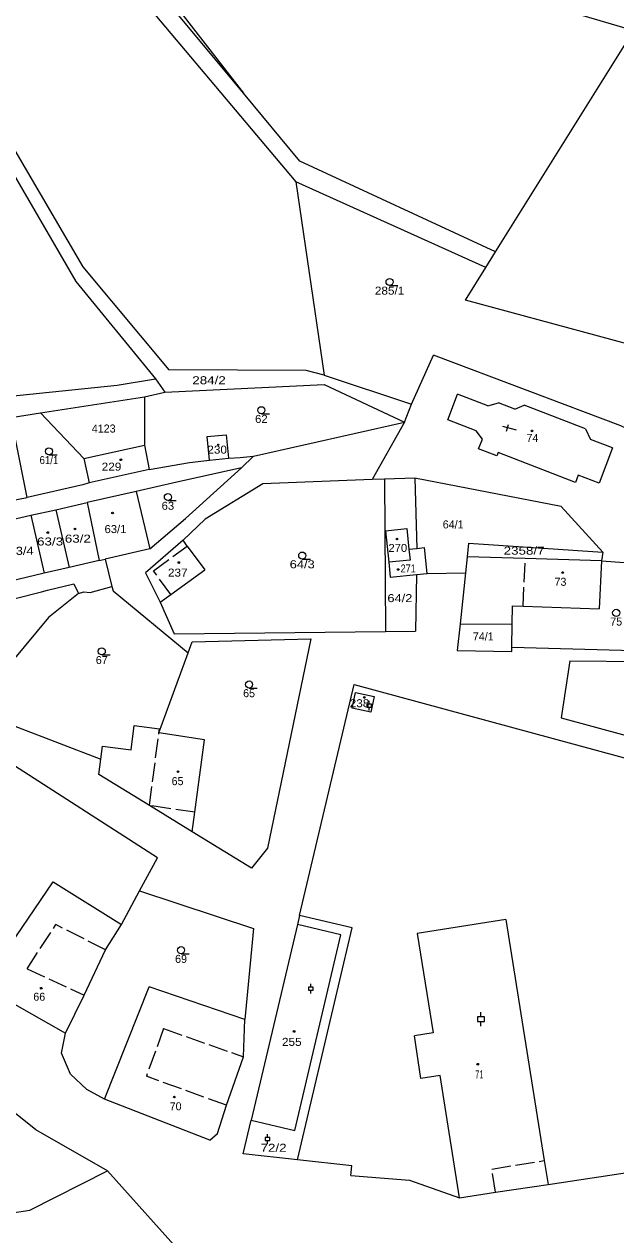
# Model space of a CAD drawing. Extents: x -590528 to -586543, y -1119609 to -1116685.
# Drawn here: x -589161.2 to -589035.6, y -1118589.8 to -1118332.6 of the extents above; entities that cross this region are included whole.
import ezdxf
from ezdxf.enums import TextEntityAlignment as Align

# ---------------------------------------------------------------- set-up
doc = ezdxf.new("R2010")
doc.units = 0
doc.header["$LTSCALE"] = 0.68
doc.linetypes.add('LONG_DASHED', pattern=[7.5, 6, -1.5])
for name, color, linetype, lineweight in [('1', 7, 'Continuous', 13), ('2', 7, 'LONG_DASHED', 13), ('3', 7, 'Continuous', 13), ('6', 7, 'Continuous', 13)]:
    doc.layers.add(name, color=color, linetype=linetype, lineweight=lineweight)

msp = doc.modelspace()

# ---------------------------------------------------------------- linework, layer by layer
at = {"layer": '1'}
for p, q in [((-589153.28, -1118297.42), (-589114.64, -1118347.32)), ((-589114.64, -1118347.32), (-589150.17, -1118304.55)), ((-589152.4, -1118308.08), (-589103.56, -1118366.12)), ((-589061.12, -1118380.96), (-589031.78, -1118334)), ((-589102.65, -1118361.74), (-589114.64, -1118347.32)), ((-589167.9, -1118351.48), (-589148.72, -1118384.16)), ((-589167.93, -1118356.86), (-589150.27, -1118387.26)), ((-589061.12, -1118380.96), (-589102.65, -1118361.74)), ((-589103.56, -1118366.12), (-589097.53, -1118407.21)), ((-589063.22, -1118384.32), (-589103.56, -1118366.12)), ((-589148.72, -1118384.16), (-589130.5, -1118406.04)), ((-589150.27, -1118387.26), (-589133.34, -1118408)), ((-589015.88, -1118405.31), (-589067.54, -1118391.23)), ((-589141.45, -1118409.35), (-589133.34, -1118408)), ((-589133.34, -1118408), (-589131.35, -1118410.84)), ((-589157.76, -1118415.19), (-589135.66, -1118411.8)), ((-589135.66, -1118411.8), (-589135.68, -1118422.1)), ((-589135.66, -1118411.8), (-589131.35, -1118410.84)), ((-589071.29, -1118416.65), (-589069.19, -1118411.22)), ((-589062.75, -1118413.71), (-589069.19, -1118411.22)), ((-589080.44, -1118417.2), (-589078.97, -1118413.35)), ((-589062.75, -1118413.71), (-589060.48, -1118413.09)), ((-589057.03, -1118414.42), (-589060.48, -1118413.09)), ((-589057.03, -1118414.42), (-589055.09, -1118413.56)), ((-589042.03, -1118418.61), (-589055.09, -1118413.56)), ((-589112.51, -1118424.43), (-589080.44, -1118417.2)), ((-589080.44, -1118417.2), (-589087.36, -1118429.39)), ((-589122.33, -1118420.22), (-589118.29, -1118419.85)), ((-589121.84, -1118425.25), (-589122.33, -1118420.22)), ((-589118.29, -1118419.85), (-589117.84, -1118424.81)), ((-589042.03, -1118418.61), (-589040.96, -1118420.85)), ((-589148.57, -1118424.88), (-589135.68, -1118422.1)), ((-589036.27, -1118422.66), (-589040.96, -1118420.85)), ((-589036.27, -1118422.66), (-589039.15, -1118430.14)), ((-589134.69, -1118427.23), (-589147.43, -1118430.1)), ((-589110.54, -1118430.26), (-589122.76, -1118437.82)), ((-589078.27, -1118429.07), (-589084.74, -1118429.29)), ((-589084.74, -1118429.29), (-589084.51, -1118461.62)), ((-589078.27, -1118429.07), (-589077.86, -1118444.01)), ((-589047.2, -1118435.13), (-589078.27, -1118429.07)), ((-589137.4, -1118431.91), (-589147.85, -1118434.23)), ((-589154.47, -1118435.78), (-589151.66, -1118448.03)), ((-589038.33, -1118444.77), (-589047.2, -1118435.13)), ((-589159.81, -1118436.94), (-589156.96, -1118449.29)), ((-589084.49, -1118440.28), (-589079.96, -1118439.8)), ((-589126.59, -1118443.49), (-589127.48, -1118442.24)), ((-589126.59, -1118443.49), (-589122.87, -1118448.58)), ((-589075.66, -1118449.31), (-589076.23, -1118443.84)), ((-589066.87, -1118442.9), (-589067.17, -1118445.79)), ((-589130.07, -1118453.82), (-589122.87, -1118448.58)), ((-589038.65, -1118446.61), (-589039.11, -1118456.83)), ((-589038.65, -1118446.61), (-589028.7, -1118447.34)), ((-589077.94, -1118449.55), (-589078.1, -1118461.55)), ((-589075.66, -1118449.31), (-589067.53, -1118449.18)), ((-589149.64, -1118453.61), (-589156.03, -1118458.71)), ((-589142.33, -1118452.99), (-589126.4, -1118466.21)), ((-589132.3, -1118455.45), (-589129.34, -1118462.16)), ((-589129.34, -1118462.16), (-589084.51, -1118461.62)), ((-589084.51, -1118461.62), (-589078.1, -1118461.55)), ((-589068.67, -1118460), (-589069.26, -1118465.68)), ((-589068.67, -1118460), (-589057.59, -1118460.07)), ((-589126.4, -1118466.21), (-589125.54, -1118463.86)), ((-589125.54, -1118463.86), (-589100.35, -1118463.18)), ((-589100.35, -1118463.18), (-589109.53, -1118507.69)), ((-589132.6, -1118483.21), (-589126.4, -1118466.21)), ((-589069.26, -1118465.68), (-589057.67, -1118465.91)), ((-589045.35, -1118467.89), (-589026.16, -1118468.09)), ((-589102.75, -1118521.96), (-589091.18, -1118472.91)), ((-589091.18, -1118472.91), (-589000.8, -1118497.42)), ((-589090.86, -1118474.63), (-589086.9, -1118475.48)), ((-589086.9, -1118475.48), (-589087.61, -1118478.8)), ((-589138.51, -1118486.77), (-589137.84, -1118481.62)), ((-589137.84, -1118481.62), (-589132.48, -1118482.32)), ((-589132.6, -1118483.21), (-589132.48, -1118482.32)), ((-589122.95, -1118484.69), (-589132.6, -1118483.21)), ((-589144.56, -1118485.98), (-589138.51, -1118486.77)), ((-589132.93, -1118509.71), (-589165.25, -1118488.91)), ((-589109.53, -1118507.69), (-589112.97, -1118511.91)), ((-589136.72, -1118516.75), (-589132.93, -1118509.71)), ((-589167.8, -1118533.6), (-589155.06, -1118514.8)), ((-589155.06, -1118514.8), (-589140.57, -1118523.88)), ((-589140.57, -1118523.88), (-589136.72, -1118516.75)), ((-589136.72, -1118516.75), (-589112.54, -1118524.74)), ((-589058.98, -1118522.83), (-589077.74, -1118525.83)), ((-589058.98, -1118522.83), (-589050.8, -1118574.06)), ((-589077.74, -1118525.83), (-589074.37, -1118546.94)), ((-589168.47, -1118537.9), (-589152.41, -1118547.01)), ((-589144.16, -1118561.01), (-589134.7, -1118537.15)), ((-589074.37, -1118546.94), (-589078.35, -1118547.53)), ((-589077, -1118556.61), (-589078.35, -1118547.53)), ((-589072.92, -1118556.01), (-589077, -1118556.61)), ((-589068.78, -1118581.94), (-589072.92, -1118556.01)), ((-589144.16, -1118561.01), (-589147.93, -1118558.92)), ((-589121.77, -1118569.69), (-589144.16, -1118561.01)), ((-589049.99, -1118579.12), (-588997.04, -1118571.17)), ((-589050.8, -1118574.06), (-589049.99, -1118579.12)), ((-589143.49, -1118576.26), (-589127.02, -1118594.64)), ((-589091.89, -1118577.25), (-589091.66, -1118575.18)), ((-589091.89, -1118577.25), (-589079.41, -1118578.2)), ((-589079.41, -1118578.2), (-589068.78, -1118581.94))]:
    msp.add_line(p, q, dxfattribs=at)
for points in [[(-589052.2, -1118327.94), (-589031.78, -1118334), (-589013.6, -1118339.4)], [(-589067.54, -1118391.23), (-589063.22, -1118384.32), (-589061.12, -1118380.96)], [(-589097.53, -1118407.21), (-589078.97, -1118413.35), (-589074.33, -1118402.95)], [(-589021.38, -1118424.19), (-589034.56, -1118417.94), (-589074.33, -1118402.95)], [(-589097.53, -1118407.21), (-589101.35, -1118406.21), (-589130.5, -1118406.04)], [(-589201.73, -1118421.4), (-589178.17, -1118413.95), (-589164.81, -1118411.74), (-589141.45, -1118409.35)], [(-589131.35, -1118410.84), (-589097.55, -1118409.16), (-589080.44, -1118417.2)], [(-589163.94, -1118416.17), (-589157.76, -1118415.19), (-589148.57, -1118424.88)], [(-589178.39, -1118436.62), (-589173.34, -1118434.64), (-589168.8, -1118433.71), (-589167.16, -1118433.45), (-589166.32, -1118433.19), (-589166.08, -1118434.28), (-589160.56, -1118433.2), (-589163.94, -1118416.17)], [(-589063.92, -1118420.79), (-589065.23, -1118419), (-589071.29, -1118416.65)], [(-589135.68, -1118422.1), (-589134.69, -1118427.23), (-589126.14, -1118425.77), (-589121.84, -1118425.25), (-589117.84, -1118424.81), (-589115.33, -1118424.71), (-589112.51, -1118424.43), (-589115.07, -1118426.91), (-589128.83, -1118429.96), (-589137.4, -1118431.91)], [(-589039.15, -1118430.14), (-589043.59, -1118428.43), (-589044.18, -1118429.97), (-589060.56, -1118423.62), (-589060.87, -1118424.32), (-589064.72, -1118422.82), (-589063.92, -1118420.79)], [(-589148.57, -1118424.88), (-589147.43, -1118430.1), (-589148.73, -1118430.47), (-589160.56, -1118433.2)], [(-589134.55, -1118444.09), (-589126.99, -1118437.66), (-589115.07, -1118426.91)], [(-589084.74, -1118429.29), (-589087.36, -1118429.39), (-589110.54, -1118430.26)], [(-589137.4, -1118431.91), (-589134.55, -1118444.09), (-589144.02, -1118446.27)], [(-589199.68, -1118448.07), (-589194.46, -1118445.28), (-589188.61, -1118443.7), (-589176.77, -1118440.88), (-589167.18, -1118438.67), (-589159.81, -1118436.94), (-589154.47, -1118435.78), (-589147.85, -1118434.23), (-589145.26, -1118446.55), (-589151.66, -1118448.03), (-589156.96, -1118449.29), (-589164.32, -1118451), (-589166.12, -1118451.49)], [(-589122.76, -1118437.82), (-589127.48, -1118442.24), (-589135.47, -1118449.21)], [(-589084.49, -1118440.28), (-589083.8, -1118446.94), (-589083.47, -1118450.12)], [(-589079.96, -1118439.8), (-589079.51, -1118444.18), (-589079.27, -1118446.47), (-589083.8, -1118446.94)], [(-589079.51, -1118444.18), (-589077.86, -1118444.01), (-589076.23, -1118443.84)], [(-589066.87, -1118442.9), (-589038.33, -1118444.77), (-589038.65, -1118446.61)], [(-589145.26, -1118446.55), (-589144.02, -1118446.27), (-589142.56, -1118452.06)], [(-589067.17, -1118445.79), (-589067.53, -1118449.18), (-589068.67, -1118460)], [(-589038.65, -1118446.61), (-589054.82, -1118446.15), (-589067.17, -1118445.79)], [(-589198.65, -1118463.65), (-589157.55, -1118453.25), (-589156.26, -1118452.88), (-589150.64, -1118451.54), (-589149.64, -1118453.61), (-589148.53, -1118453.2), (-589147.22, -1118453.38), (-589142.56, -1118452.06), (-589142.33, -1118452.99)], [(-589135.47, -1118449.21), (-589132.3, -1118455.45), (-589130.07, -1118453.82)], [(-589083.47, -1118450.12), (-589077.94, -1118449.55), (-589075.66, -1118449.31)], [(-589057.67, -1118464.97), (-589057.59, -1118460.07), (-589057.52, -1118456.21)], [(-589057.52, -1118456.21), (-589055.29, -1118456.29), (-589039.11, -1118456.83)], [(-589156.03, -1118458.71), (-589171.27, -1118476.97), (-589171.51, -1118478.56)], [(-589057.67, -1118465.91), (-589057.67, -1118464.97), (-589029.21, -1118465.75)], [(-589045.35, -1118467.89), (-589047.21, -1118480.01), (-589019.57, -1118487.48)], [(-589087.61, -1118478.8), (-589091.58, -1118477.95), (-589090.86, -1118474.63)], [(-589171.51, -1118478.56), (-589144.92, -1118488.74), (-589144.56, -1118485.98)], [(-589125.55, -1118504.19), (-589125, -1118500.04), (-589122.95, -1118484.69)], [(-589134.62, -1118498.63), (-589145.35, -1118492.04), (-589144.92, -1118488.74)], [(-589112.97, -1118511.91), (-589125.55, -1118504.19), (-589134.62, -1118498.63)], [(-589102.75, -1118521.96), (-589103.21, -1118523.91), (-589113.01, -1118565.47)], [(-589103.19, -1118573.9), (-589091.56, -1118524.6), (-589102.75, -1118521.96)], [(-589152.41, -1118547.01), (-589148.46, -1118538.94), (-589143.96, -1118529.29), (-589140.57, -1118523.88)], [(-589112.54, -1118524.74), (-589114.37, -1118544.06), (-589134.7, -1118537.15)], [(-589103.77, -1118567.65), (-589093.97, -1118526.09), (-589103.21, -1118523.91)], [(-589118.24, -1118562.29), (-589114.62, -1118552.01), (-589114.37, -1118544.06)], [(-589147.93, -1118558.92), (-589151.39, -1118555.72), (-589153.29, -1118551.24), (-589152.41, -1118547.01)], [(-589158.76, -1118567.49), (-589164.81, -1118562.6), (-589166.2, -1118566)], [(-589121.77, -1118569.69), (-589120.17, -1118568.3), (-589118.24, -1118562.29)], [(-589114.7, -1118572.62), (-589113.01, -1118565.47), (-589103.77, -1118567.65)], [(-589169.24, -1118585.88), (-589167.08, -1118585.66), (-589159.98, -1118584.55), (-589143.49, -1118576.26), (-589158.76, -1118567.49)], [(-589091.66, -1118575.18), (-589103.19, -1118573.9), (-589114.7, -1118572.62)], [(-589068.78, -1118581.94), (-589061.15, -1118580.79), (-589049.99, -1118579.12)]]:
    msp.add_lwpolyline(points, dxfattribs=at)
at = {"layer": '2'}
for p, q in [((-589055.29, -1118456.29), (-589054.82, -1118446.15)), ((-589160.6, -1118533.28), (-589154.45, -1118523.92)), ((-589143.96, -1118529.29), (-589154.45, -1118523.92)), ((-589160.6, -1118533.28), (-589148.46, -1118538.94)), ((-589131.6, -1118546.02), (-589135.26, -1118556.13)), ((-589131.6, -1118546.02), (-589114.62, -1118552.01)), ((-589118.24, -1118562.29), (-589135.26, -1118556.13)), ((-589061.94, -1118575.84), (-589050.8, -1118574.06)), ((-589061.15, -1118580.79), (-589061.94, -1118575.84))]:
    msp.add_line(p, q, dxfattribs=at)
for points in [[(-589130.07, -1118453.82), (-589133.78, -1118448.73), (-589126.59, -1118443.49)], [(-589125, -1118500.04), (-589134.62, -1118498.63), (-589132.6, -1118483.21)]]:
    msp.add_lwpolyline(points, dxfattribs=at)
at = {"layer": '6'}
for p, q in [((-589083.63, -1118388.14), (-589081.88, -1118388.14)), ((-589110.85, -1118415.39), (-589109.1, -1118415.39)), ((-589056.669, -1118418.901), (-589059.565, -1118418.119)), ((-589058.796, -1118419.104), (-589058.404, -1118417.656)), ((-589155.95, -1118424.13), (-589154.2, -1118424.13)), ((-589130.69, -1118433.84), (-589128.94, -1118433.84)), ((-589102.18, -1118446.27), (-589100.43, -1118446.27)), ((-589144.73, -1118466.62), (-589142.98, -1118466.62)), ((-589113.46, -1118473.66), (-589111.71, -1118473.66)), ((-589087.96, -1118477.085), (-589087.96, -1118476.415)), ((-589087.96, -1118478.425), (-589087.96, -1118477.755)), ((-589127.9, -1118530.1), (-589126.15, -1118530.1)), ((-589100.35, -1118537.195), (-589100.35, -1118536.525)), ((-589100.35, -1118538.535), (-589100.35, -1118537.865)), ((-589064.23, -1118543.52), (-589064.23, -1118542.52)), ((-589064.23, -1118545.52), (-589064.23, -1118544.52)), ((-589109.54, -1118569.125), (-589109.54, -1118568.455)), ((-589109.54, -1118570.465), (-589109.54, -1118569.795))]:
    msp.add_line(p, q, dxfattribs=at)
for points in [[(-589088.462, -1118477.755), (-589087.458, -1118477.755), (-589087.458, -1118477.085), (-589088.462, -1118477.085)], [(-589100.852, -1118537.865), (-589099.848, -1118537.865), (-589099.848, -1118537.195), (-589100.852, -1118537.195)], [(-589064.98, -1118544.52), (-589063.48, -1118544.52), (-589063.48, -1118543.52), (-589064.98, -1118543.52)], [(-589110.042, -1118569.795), (-589109.038, -1118569.795), (-589109.038, -1118569.125), (-589110.042, -1118569.125)]]:
    msp.add_lwpolyline(points, close=True, dxfattribs=at)
for centre, radius in [((-589083.63, -1118387.39), 0.75), ((-589110.85, -1118414.64), 0.75), ((-589053.3802, -1118419.0304), 0.175), ((-589155.95, -1118423.38), 0.75), ((-589120.0001, -1118421.9702), 0.1172), ((-589140.6802, -1118425.1704), 0.175), ((-589130.69, -1118433.09), 0.75), ((-589142.4402, -1118436.4904), 0.175), ((-589156.1902, -1118440.6304), 0.175), ((-589150.4202, -1118439.8604), 0.175), ((-589082.0602, -1118442.0004), 0.175), ((-589102.18, -1118445.52), 0.75), ((-589128.3702, -1118447.0004), 0.175), ((-589081.7902, -1118448.4804), 0.175), ((-589046.8802, -1118449.1204), 0.175), ((-589035.52, -1118457.69), 0.75), ((-589144.73, -1118465.87), 0.75), ((-589113.46, -1118472.91), 0.75), ((-589089.0002, -1118475.6604), 0.175), ((-589128.5602, -1118491.4404), 0.175), ((-589127.9, -1118529.35), 0.75), ((-589157.5902, -1118537.4304), 0.175), ((-589103.9002, -1118546.6204), 0.175), ((-589064.9002, -1118553.5804), 0.175), ((-589129.3102, -1118560.5604), 0.175)]:
    msp.add_circle(centre, radius, dxfattribs=at)

# ---------------------------------------------------------------- texts
at = {"layer": '3'}
for s, width, p in [('285/1', 1.1, (-589083.63, -1118390.09)), ('284/2', 1.25, (-589121.96, -1118409.12)), ('62', 1.05, (-589110.851, -1118417.34)), ('230', 1.1, (-589120.2405, -1118423.86)), ('61/1', 0.9, (-589155.9505, -1118426.08)), ('229', 1.1, (-589142.66, -1118427.48)), ('63', 1.05, (-589130.6905, -1118435.79)), ('63/2', 1.25, (-589149.8105, -1118442.77)), ('63/1', 1.05, (-589141.8205, -1118440.74)), ('63/4', 1.2, (-589161.8505, -1118445.36)), ('63/3', 1.25, (-589155.7015, -1118443.38)), ('270', 1.05, (-589081.88, -1118444.75)), ('2358/7', 1.25, (-589055.0705, -1118445.33)), ('64/3', 1.2, (-589102.1805, -1118448.22)), ('237', 1.1, (-589128.6005, -1118449.99)), ('271', 0.85, (-589079.6805, -1118449.11)), ('64/2', 1.2, (-589081.44, -1118455.41)), ('238', 1.1, (-589090.01, -1118477.74)), ('255', 1.1, (-589104.3905, -1118549.68)), ('71', 0.7, (-589064.5805, -1118556.59)), ('72/2', 1.25, (-589108.2605, -1118572.18))]:
    msp.add_text(s, height=1.7, dxfattribs=dict(at, width=width)).set_placement(p, align=Align.CENTER)
for s, p in [('4123', (-589144.32, -1118419.38)), ('74', (-589053.3005, -1118421.38)), ('64/1', (-589070.1305, -1118439.75)), ('73', (-589047.3605, -1118451.94)), ('75', (-589035.5205, -1118460.39)), ('74/1', (-589063.7405, -1118463.54)), ('67', (-589144.7305, -1118468.57)), ('65', (-589113.4605, -1118475.61)), ('65', (-589128.6405, -1118494.29)), ('69', (-589127.9005, -1118532.05)), ('66', (-589158.0005, -1118540.09)), ('70', (-589129.05, -1118563.37))]:
    msp.add_text(s, height=1.7, dxfattribs=at).set_placement(p, align=Align.CENTER)

doc.saveas('drawing.dxf')
